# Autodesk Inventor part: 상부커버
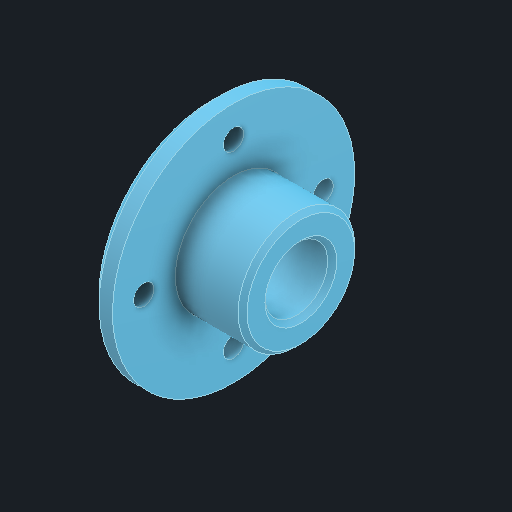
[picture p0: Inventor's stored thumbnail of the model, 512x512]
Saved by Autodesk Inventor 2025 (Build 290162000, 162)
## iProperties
Created: 2025-08
Part Number: 상부커버
Material: 알루미늄 6061
Document SubType Name: Modeling
Designer: infra002
Density: 2.71 g/cm^3
Appearance: 기본값
Author: jhkim
Sending System: Autodesk Inventor 2026
Preprocessor: ST-DEVELOPER v20.1
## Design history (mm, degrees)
feature "솔리드1"
node "솔리드2"
